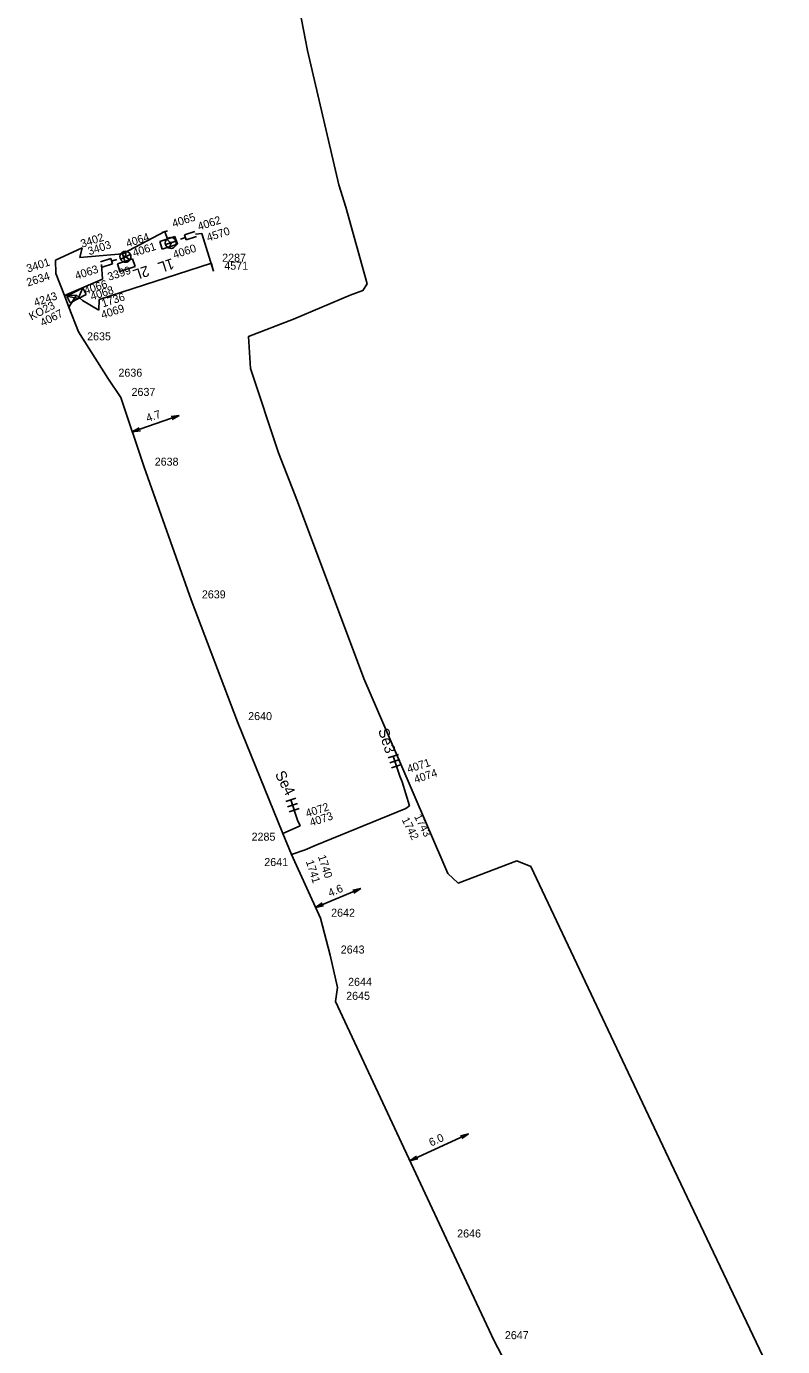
# Model space of a CAD drawing. Extents: x -535557 to -534097, y -1142175 to -1136716.
# Drawn here: x -535467.8 to -535396.9, y -1138341.2 to -1138217.5 of the extents above; entities that cross this region are included whole.
import ezdxf

# ---------------------------------------------------------------- set-up
doc = ezdxf.new("R2010")
doc.units = 0
for name, color, linetype in [('Default', 7, 'Continuous'), ('GIS_vektor_sdelovaci_kabely_CD', 7, 'Continuous'), ('SS_SZDC', 7, 'Continuous')]:
    doc.layers.add(name, color=color, linetype=linetype)

# ---------------------------------------------------------------- blocks, each defined once
blk = doc.blocks.new('POINT_DISPLAY')
at = {"layer": 'Default'}
blk.add_line((0, 0), (0, 0), dxfattribs=at)

msp = doc.modelspace()

# ---------------------------------------------------------------- linework, layer by layer
at = {"layer": 'GIS_vektor_sdelovaci_kabely_CD'}
msp.add_lwpolyline([(-535442.743, -1138212.918), (-535441.455, -1138219.732), (-535438.502, -1138232.316), (-535437.84, -1138234.423), (-535435.863, -1138241.609), (-535436.244, -1138242.217), (-535437.455, -1138242.67), (-535442.74, -1138244.921), (-535446.963, -1138246.53), (-535446.775, -1138249.537), (-535444.151, -1138257.438), (-535442.383, -1138262.02), (-535436.161, -1138278.591), (-535431.828, -1138288.659), (-535428.286, -1138296.889), (-535427.336, -1138297.782), (-535421.819, -1138295.678), (-535420.507, -1138296.227), (-535407.099, -1138324.648), (-535396.93, -1138346)], dxfattribs=at)
at = {"layer": 'SS_SZDC'}
for p, q in [((-535458.779, -1138238.78), (-535454.81, -1138236.7)), ((-535453.861, -1138237.175), (-535455.285, -1138237.648)), ((-535454.572, -1138236.621), (-535455.047, -1138236.778)), ((-535454.81, -1138236.7), (-535454.573, -1138237.411)), ((-535454.636, -1138237.419), (-535454.509, -1138237.325)), ((-535454.509, -1138237.325), (-535454.319, -1138237.263)), ((-535454.319, -1138237.263), (-535454.05, -1138237.281)), ((-535454.05, -1138237.281), (-535453.909, -1138237.393)), ((-535453.625, -1138237.887), (-535453.861, -1138237.175)), ((-535452.881, -1138237.249), (-535453.356, -1138237.403)), ((-535452.958, -1138237.011), (-535452.007, -1138236.702)), ((-535452.803, -1138237.486), (-535452.958, -1138237.011)), ((-535451.852, -1138237.177), (-535452.803, -1138237.486)), ((-535451.329, -1138236.87), (-535451.93, -1138236.94)), ((-535450.239, -1138240.43), (-535451.329, -1138236.87)), ((-535462.569, -1138238.229), (-535465.05, -1138239.389)), ((-535462.76, -1138239.12), (-535462.569, -1138238.229)), ((-535458.816, -1138238.669), (-535458.637, -1138238.579)), ((-535458.637, -1138238.579), (-535458.481, -1138238.555)), ((-535458.481, -1138238.555), (-535458.302, -1138238.576)), ((-535458.479, -1138238.779), (-535458.481, -1138238.555)), ((-535458.302, -1138238.576), (-535458.099, -1138238.753)), ((-535455.285, -1138237.648), (-535455.048, -1138238.359)), ((-535455.048, -1138238.359), (-535453.625, -1138237.887)), ((-535454.766, -1138237.829), (-535454.748, -1138237.56)), ((-535454.704, -1138238.019), (-535454.766, -1138237.829)), ((-535454.748, -1138237.56), (-535454.636, -1138237.419)), ((-535454.735, -1138237.924), (-535453.784, -1138237.615)), ((-535454.532, -1138238.226), (-535454.704, -1138238.019)), ((-535454.479, -1138237.578), (-535454.636, -1138237.419)), ((-535454.358, -1138238.275), (-535454.532, -1138238.226)), ((-535454.338, -1138237.69), (-535454.479, -1138237.578)), ((-535454.325, -1138238.054), (-535454.358, -1138238.275)), ((-535454.2, -1138238.276), (-535454.358, -1138238.275)), ((-535454.164, -1138237.739), (-535454.338, -1138237.69)), ((-535454.276, -1138237.88), (-535454.325, -1138238.054)), ((-535454.164, -1138237.739), (-535454.276, -1138237.88)), ((-535454.01, -1138238.214), (-535454.2, -1138238.276)), ((-535453.803, -1138238.042), (-535454.01, -1138238.214)), ((-535453.909, -1138237.393), (-535453.815, -1138237.52)), ((-535453.815, -1138237.52), (-535453.753, -1138237.71)), ((-535453.754, -1138237.868), (-535453.803, -1138238.042)), ((-535453.753, -1138237.71), (-535453.754, -1138237.868)), ((-535465.05, -1138239.389), (-535465.02, -1138240.639)), ((-535462.76, -1138239.12), (-535458.779, -1138238.78)), ((-535460.96, -1138243.069), (-535450.439, -1138239.68)), ((-535460.827, -1138239.552), (-535459.876, -1138239.243)), ((-535460.75, -1138239.79), (-535460.659, -1138241.17)), ((-535459.721, -1138239.718), (-535460.672, -1138240.027)), ((-535459.876, -1138239.243), (-535459.721, -1138239.718)), ((-535459.798, -1138239.48), (-535459.323, -1138239.326)), ((-535457.831, -1138239.255), (-535459.255, -1138239.728)), ((-535459.255, -1138239.728), (-535459.018, -1138240.439)), ((-535458.542, -1138238.701), (-535459.017, -1138238.858)), ((-535459.014, -1138239.051), (-535458.993, -1138238.872)), ((-535458.99, -1138239.207), (-535459.014, -1138239.051)), ((-535458.993, -1138238.872), (-535458.816, -1138238.669)), ((-535458.9, -1138239.386), (-535458.99, -1138239.207)), ((-535458.054, -1138238.843), (-535458.945, -1138239.296)), ((-535458.787, -1138239.497), (-535458.9, -1138239.386)), ((-535458.63, -1138239.585), (-535458.787, -1138239.497)), ((-535458.779, -1138238.78), (-535458.543, -1138239.491)), ((-535458.362, -1138239.56), (-535458.63, -1138239.585)), ((-535458.589, -1138239.115), (-535458.5, -1138238.958)), ((-535458.589, -1138239.115), (-535458.41, -1138239.136)), ((-535458.5, -1138238.958), (-535458.479, -1138238.779)), ((-535458.41, -1138239.136), (-535458.252, -1138239.224)), ((-535458.183, -1138239.47), (-535458.362, -1138239.56)), ((-535458.252, -1138239.224), (-535458.072, -1138239.357)), ((-535458.072, -1138239.357), (-535458.183, -1138239.47)), ((-535458.099, -1138238.753), (-535458.009, -1138238.932)), ((-535457.984, -1138239.2), (-535458.072, -1138239.357)), ((-535458.009, -1138238.932), (-535457.984, -1138239.2)), ((-535457.595, -1138239.967), (-535457.831, -1138239.255)), ((-535450.439, -1138239.68), (-535450.239, -1138240.43)), ((-535465.02, -1138240.639), (-535464.22, -1138242.7)), ((-535459.018, -1138240.439), (-535457.595, -1138239.967)), ((-535460.659, -1138241.17), (-535464.219, -1138242.7)), ((-535464.006, -1138242.754), (-535462.491, -1138241.982)), ((-535462.931, -1138242.991), (-535462.491, -1138241.982)), ((-535462.491, -1138241.982), (-535462.173, -1138242.605)), ((-535464.22, -1138242.7), (-535463.819, -1138243.78)), ((-535464.219, -1138242.7), (-535463.09, -1138242.68)), ((-535463.688, -1138243.377), (-535464.006, -1138242.754)), ((-535464.006, -1138242.754), (-535462.931, -1138242.991)), ((-535463.09, -1138242.68), (-535463.819, -1138243.78)), ((-535462.173, -1138242.605), (-535463.688, -1138243.377)), ((-535463.09, -1138242.68), (-535462.51, -1138243.159)), ((-535462.51, -1138243.159), (-535461, -1138244.069)), ((-535461, -1138244.069), (-535460.96, -1138243.069)), ((-535463.819, -1138243.78), (-535462.909, -1138246.1)), ((-535462.909, -1138246.1), (-535460.159, -1138250.459)), ((-535460.159, -1138250.459), (-535458.93, -1138252.26)), ((-535458.93, -1138252.26), (-535456.76, -1138258.799)), ((-535457.86, -1138255.484), (-535453.468, -1138253.935)), ((-535454.225, -1138254.043), (-535453.468, -1138253.935)), ((-535453.468, -1138253.935), (-535454.125, -1138254.326)), ((-535457.86, -1138255.484), (-535457.202, -1138255.093)), ((-535457.102, -1138255.376), (-535457.86, -1138255.484)), ((-535456.76, -1138258.799), (-535452.34, -1138271.239)), ((-535452.34, -1138271.239), (-535448, -1138282.649)), ((-535448, -1138282.649), (-535443.75, -1138293.129)), ((-535433.883, -1138286.022), (-535432.932, -1138285.713)), ((-535433.729, -1138286.497), (-535432.777, -1138286.188)), ((-535433.574, -1138286.973), (-535432.623, -1138286.664)), ((-535432.789, -1138287.77), (-535433.408, -1138285.867)), ((-535432.789, -1138287.77), (-535432.569, -1138288.299)), ((-535432.569, -1138288.299), (-535431.88, -1138290.54)), ((-535443.473, -1138290.142), (-535442.522, -1138289.833)), ((-535443.319, -1138290.617), (-535442.367, -1138290.308)), ((-535442.38, -1138291.889), (-535442.998, -1138289.987)), ((-535432.22, -1138290.799), (-535431.88, -1138290.54)), ((-535443.164, -1138291.093), (-535442.213, -1138290.784)), ((-535440.71, -1138294.239), (-535432.22, -1138290.799)), ((-535442.14, -1138292.42), (-535443.75, -1138293.129)), ((-535442.38, -1138291.889), (-535442.14, -1138292.42)), ((-535443.75, -1138293.129), (-535442.949, -1138295.1)), ((-535441.67, -1138294.659), (-535440.71, -1138294.239)), ((-535441.67, -1138294.659), (-535442.949, -1138295.1)), ((-535442.949, -1138295.1), (-535440.229, -1138301.079)), ((-535440.693, -1138300.061), (-535436.456, -1138298.29)), ((-535437.206, -1138298.441), (-535436.456, -1138298.29)), ((-535436.456, -1138298.29), (-535437.09, -1138298.718)), ((-535440.693, -1138300.061), (-535440.059, -1138299.633)), ((-535439.943, -1138299.91), (-535440.693, -1138300.061)), ((-535440.229, -1138301.079), (-535439.329, -1138304.53)), ((-535439.329, -1138304.53), (-535438.64, -1138307.559)), ((-535438.64, -1138307.559), (-535438.819, -1138308.87)), ((-535438.819, -1138308.87), (-535428.42, -1138331.149)), ((-535431.842, -1138323.817), (-535426.35, -1138321.284)), ((-535427.094, -1138321.461), (-535426.35, -1138321.284)), ((-535426.35, -1138321.284), (-535426.968, -1138321.734)), ((-535431.842, -1138323.817), (-535431.224, -1138323.367)), ((-535431.098, -1138323.639), (-535431.842, -1138323.817)), ((-535428.42, -1138331.149), (-535423.949, -1138340.68)), ((-535423.949, -1138340.68), (-535421.739, -1138344.889))]:
    msp.add_line(p, q, dxfattribs=at)

# ---------------------------------------------------------------- block references
for p in [(-535454.81, -1138236.7), (-535451.93, -1138236.94), (-535451.329, -1138236.87), (-535462.569, -1138238.229), (-535454.26, -1138237.77), (-535465.05, -1138239.389), (-535462.76, -1138239.12), (-535460.75, -1138239.79), (-535458.779, -1138238.78), (-535458.5, -1138239.069), (-535450.439, -1138239.68), (-535465.02, -1138240.639), (-535450.239, -1138240.43), (-535460.659, -1138241.17), (-535464.22, -1138242.7), (-535463.09, -1138242.68), (-535462.51, -1138243.159), (-535460.96, -1138243.069), (-535463.819, -1138243.78), (-535461, -1138244.069), (-535462.909, -1138246.1), (-535460.159, -1138250.459), (-535458.93, -1138252.26), (-535456.76, -1138258.799), (-535452.34, -1138271.239), (-535448, -1138282.649), (-535432.789, -1138287.77), (-535432.569, -1138288.299), (-535431.88, -1138290.54), (-535432.22, -1138290.799), (-535442.38, -1138291.889), (-535442.14, -1138292.42), (-535443.75, -1138293.129), (-535440.71, -1138294.239), (-535442.949, -1138295.1), (-535441.67, -1138294.659), (-535440.229, -1138301.079), (-535439.329, -1138304.53), (-535438.64, -1138307.559), (-535438.819, -1138308.87), (-535428.42, -1138331.149), (-535423.949, -1138340.68)]:
    msp.add_blockref('POINT_DISPLAY', p, dxfattribs=at)

# ---------------------------------------------------------------- texts
for s, height, rotation, p in [('4065', 0.75, 18, (-535453.99, -1138236.334)), ('4062', 0.75, 18, (-535451.6, -1138236.613)), ('3402', 0.75, 18, (-535462.569, -1138238.229)), ('4064', 0.75, 18, (-535458.312, -1138238.195)), ('4570', 0.75, 18, (-535450.764, -1138237.647)), ('3403', 0.75, 18, (-535461.893, -1138238.93)), ('4061', 0.75, 18, (-535457.686, -1138239.082)), ('4060', 0.75, 18, (-535453.92, -1138239.256)), ('3401', 0.75, 18, (-535467.633, -1138240.552)), ('1L', 1, 198.37566, (-535454.141, -1138239.193)), ('2634', 0.75, 18, (-535467.633, -1138241.86)), ('4063', 0.75, 18, (-535463.096, -1138241.222)), ('3399', 0.75, 18, (-535460.041, -1138241.324)), ('2L', 1, 198.37566, (-535456.479, -1138239.875)), ('4066', 0.75, 18, (-535462.238, -1138242.605)), ('4068', 0.75, 18, (-535461.652, -1138243.17)), ('KO23', 0.75, 27.37566, (-535467.305, -1138245.05)), ('4243', 0.75, 18, (-535466.948, -1138243.74)), ('4069', 0.75, 18, (-535460.652, -1138244.894)), ('1736', 0.75, 18, (-535460.602, -1138243.815)), ('4067', 0.75, 27, (-535466.256, -1138245.626)), ('4.7', 0.75, 19.42898, (-535456.42, -1138254.578)), ('Se3', 1, 288, (-535434.839, -1138283.447)), ('4071', 0.75, 18, (-535431.977, -1138287.468)), ('Se4', 1, 297, (-535444.519, -1138287.557)), ('4074', 0.75, 18, (-535431.333, -1138288.434)), ('4072', 0.75, 18, (-535441.478, -1138291.622)), ('4073', 0.75, 18, (-535441.108, -1138292.476)), ('1742', 0.75, 297, (-535432.644, -1138291.832)), ('1743', 0.75, 297, (-535431.473, -1138291.539)), ('1740', 0.75, 288, (-535440.474, -1138295.271)), ('1741', 0.75, 288, (-535441.609, -1138295.747)), ('4.6', 0.75, 22.68472, (-535439.329, -1138299.084)), ('6.0', 0.75, 24.76276, (-535429.853, -1138322.486))]:
    msp.add_text(s, height=height, rotation=rotation, dxfattribs=at).set_placement(p)
for s, p in [('2287', (-535449.439, -1138239.53)), ('4571', (-535449.239, -1138240.28)), ('2635', (-535462.092, -1138246.903)), ('2636', (-535459.159, -1138250.309)), ('2637', (-535457.93, -1138252.11)), ('2638', (-535455.76, -1138258.649)), ('2639', (-535451.34, -1138271.089)), ('2640', (-535447, -1138282.499)), ('2285', (-535446.682, -1138293.803)), ('2641', (-535445.492, -1138296.183)), ('2642', (-535439.229, -1138300.929)), ('2643', (-535438.329, -1138304.38)), ('2644', (-535437.64, -1138307.409)), ('2645', (-535437.819, -1138308.72)), ('2646', (-535427.42, -1138330.999)), ('2647', (-535422.949, -1138340.53))]:
    msp.add_text(s, height=0.75, dxfattribs=at).set_placement(p)

doc.saveas('drawing.dxf')
